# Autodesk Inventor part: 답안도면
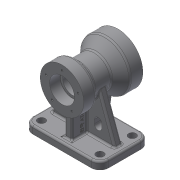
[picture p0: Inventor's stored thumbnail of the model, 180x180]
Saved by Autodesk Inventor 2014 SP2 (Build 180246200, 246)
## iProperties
Created: 2012-11
Part Number: 답안도면
Material: 일반
Document SubType Name: Modeling
Designer: 손기택
Density: 1 g/cm^3
Appearance: 기본값
Author: 손기택
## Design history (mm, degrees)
sketch "스케치1"
  geometry: L1 (-61, 40)-(61, 40); L2 (61, 40)-(61, -40); L3 (61, -40)-(-61, -40); L4 (-61, -40)-(-61, 40); 1 further point
  constraints: 8 end point, 2 parallel, 1 horizontal, 1 perpendicular
  dimensions: "d0" = 122 distance of L1.start L1.end; "d1" = 80 distance of L3.end L1.start; "d2" = 40 distance from line of L1 point (0, 0) (= 0.5 x d1); "d3" = 61 distance from line of L4 point (0, 0) (= 0.5 x d0)
extrude "돌출1" new body sketch "스케치1" distance "d4" = 12; taper "d5" = 0 deg
sketch "스케치3"
  geometry: L1 (-40, 120)-(-20, 120); L2 (-20, 120)-(-14.804, 111); L3 (-14.804, 111)-(13.315, 111); L4 (50, 125)-(50, 111); L5 (50, 111)-(30, 111); L6 (30, 111)-(30, 104); L7 (-40, 105)-(-40, 120); L8 (-54.476, 85)-(46.915, 85); L9 (40, 0)-(-40, 0) reference; L10 (13.315, 111)-(30, 125); L11 (50, 125)-(30, 125); L12 (27, 101)-(-23, 101); L13 (-23, 101)-(-23, 105); L14 (-23, 105)-(-40, 105); L15 (27, 101)-(30, 104); L16 (-40, 0)-(-40, 12) reference; 1 further point
  constraints: 28 end point, 5 parallel, 3 perpendicular, 1 horizontal
  dimensions: "d8" = 35 distance between parallel lines of L8 L1; "d9" = 85 distance between parallel lines of L9 L8; "d13" = 90 distance between parallel lines of L7 L4; "d14" = 20 distance of L1.start L1.end; "d15" = 60 deg angle of L3 L2; "d17" = 40 deg angle of L3 L10; "d18" = 40 distance from line of L4.start L8; "d19" = 20 distance of L4.start L10.end; "d20" = 26 distance between parallel lines of L8 L3; "d22" = 20 distance of L4.end L5.end; "d26" = 16 distance between parallel lines of L8 L12; "d27" = 3 distance from line of L12.start L6; "d28" = 20 distance between parallel lines of L8 L14; "d29" = 17 distance of L13.end L7.start; "d31" = 19 distance from line of L6.end L8; "d32" = 0 distance between parallel lines of L7 L16; "d33" = 26 distance between parallel lines of L5 L8
revolve "회전1" sketch "스케치3" stored, may be unused: angle "d34" = 90 deg
sketch "스케치4"
  geometry: L1 (-6, 30)-(6, 30); L2 (6, 30)-(6, -30); L3 (6, -30)-(-6, -30); L4 (-6, -30)-(-6, 30); L5 (-61, 40)-(61, 40) reference; L6 (61, -40)-(-61, -40) reference; 1 further point
  constraints: 8 end point, 2 parallel, 1 horizontal, 1 perpendicular
  dimensions: "d35" = 12 distance of L1.start L1.end; "d38" = 6 distance from line of point (0, 0) L2 (= 0.5 x d35); "d39" = 10 distance between parallel lines of L1 L5; "d40" = 10 distance between parallel lines of L6 L3
extrude "돌출2" join sketch "스케치4" stored distance "d41" = 12; taper "d42" = 0 deg
feature "면 기울기2" dims angle "d44" = 10 deg
sketch "스케치7"
  geometry: L1 (-61, 12)-(61, 12) reference; L2 (6, 12)-(6, 45.453) reference; L3 (51, 12)-(25.747, 81.382); L4 (61, 0)-(61, 12) reference; L5 (6, 12)-(6, 50.518) reference; L6 (6, 59.702)-(6, 50.518) reference; A1 r 40 centre (0, 85) between (6, 45.453) and (32.776, 62.071) reference; A2 r 26 centre (0, 85) between (6, 59.702) and (-6, 59.702) reference; 1 further point
  constraints: 2 end point, 2 point on circle, 2 point on line
  dimensions: "d45" = 10 distance from line of L4 L3.start; "d46" = 70 deg angle of L1 L3
extrude "돌출3" join sketch "스케치7" stored distance "d47" = 12; taper "d48" = 0 deg
sketch "스케치8"
  geometry: L1 (-24, 42)-(-24, 42); L2 (-18, 36)-(-18, 30); L3 (-24, 24)-(-24, 24); L4 (-30, 30)-(-30, 36); L5 (85.4, 0)-(-85.4, 0) reference; L6 (0, -25)-(0, 150) reference; A1 r 6 centre (-24, 36) between (-24, 42) and (-30, 36); A2 r 6 centre (-24, 36) between (-18, 36) and (-24, 42); A3 r 6 centre (-24, 30) between (-30, 30) and (-24, 24); A4 r 6 centre (-24, 30) between (-24, 24) and (-18, 30); 4 further points
  constraints: 8 end point, 8 point on circle, 8 tangent, 6 point on line, 4 centre point, 3 equal radius, 2 parallel, 1 horizontal, 1 perpendicular
  dimensions: "d50" = 12 distance of point (-18, 24) point (-30, 24); "d51" = 18 distance of point (-18, 42) point (-18, 24); "d53" = 6 radius of A1; "d54" = 30 distance from line of A3.centre L5; "d55" = 24 distance from line of A3.centre L6
extrude "돌출4" cut sketch "스케치8" stored distance "d56" = 12; taper "d57" = 0 deg
sketch "스케치9"
  geometry: L1 (-85.4, 0)-(85.4, 0) reference; L2 (0, -58)-(0, 68) reference; C1 r 6 at (47, 26); C2 r 6 at (47, -26); C3 r 6 at (-47, 26); C4 r 6 at (-47, -26); 1 further point
  constraints: 4 centre point, 3 symmetric about line, 3 other
  dimensions: "d58" = 26 vertical distance of C1.centre point (0, 0); "d59" = 47 horizontal distance of C1.centre point (0, 0); "d60" = 12 diameter of C1
extrude "돌출5" cut sketch "스케치9" distance "d61" = 12; taper "d62" = 0 deg
sketch "스케치10" dims "d63" = 54
  geometry: C1 r 35 at (0, 0) reference; C2 r 20 at (0, 0) reference; 7 further points
  constraints: 1 coincident, 1 vertical alignment, 8 other
  dimensions: "d99" = 27 distance of point (0, 0) point (0, 27) (derived); "d102" = 360 deg dimension on C1.centre point (0, 27) (derived)
hole "구멍1" sketch "스케치10" at (0, 27), (-25.679, 8.343), (-15.87, -21.843), (15.87, -21.843), (25.679, 8.343) diameter "d67" = 3.242; stored, may be unused: countersink angle "d71" = 90 deg, drill point angle "d73" = 118 deg; dims "d68" = 10, "d69" = 9.4, "d70" = 2, "d72" = 12
sketch "스케치11" dims "d104" = 66
  geometry: C1 r 26 at (0, 0) reference; 7 further points
  constraints: 1 coincident, 1 vertical alignment, 8 other
  dimensions: "d107" = 360 deg dimension on C1.centre point (0, -33) (derived)
hole "구멍2" sketch "스케치11" diameter "d79" = 3.242; stored, may be unused: countersink angle "d83" = 90 deg, drill point angle "d85" = 118 deg; dims "d80" = 10, "d81" = 9.4, "d82" = 2, "d84" = 12
fillet "모깎기1" dims "d86" = 14
fillet "모깎기3" dims "d91" = 3, "d92" = 3
fillet "모깎기5" dims "d94" = 5, "d95" = 0.3
chamfer "모따기1" distance "d96" = 1; stored, may be unused: second distance "d97" = 2, angle "d98" = 45 deg
sketch "스케치12"
  geometry: L1 (0.066, 10)-(-44.934, 10); L2 (-44.934, 10)-(-44.934, 16); L3 (-44.934, 16)-(0.066, 16); L4 (0.066, 16)-(0.066, 10); L5 (25, 13)-(-128, 13); L6 (-33.081, -3)-(0, -3) reference; 1 further point
  constraints: 2 end point, 1 perpendicular, 2 other
  dimensions: "d109" = 16 distance between parallel lines of L5 L6; "d110" = 45 distance of L1.start L1.end; "d111" = 6 distance of L3.end L1.start; "d112" = 3 distance between parallel lines of L1 L5
feature "엠보싱1" sketch "스케치12" dims "d0" = 122, "d1" = 80, "d2" = 40 (= 0.5 x d1), "d3" = 61 (= 0.5 x d0), "d8" = 35, "d9" = 85, "d13" = 90, "d14" = 20, "d15" = 60 deg, "d17" = 40 deg, "d18" = 40, "d19" = 20, "d20" = 26, "d22" = 20, "d26" = 16, "d27" = 3, "d28" = 20, "d29" = 17, "d31" = 19, "d32" = 0, "d33" = 26, "d113" = 0.5, "d114" = 0
node "솔리드1"
mirror "대칭1"
mirror "대칭2"
node "투영된 루프1"
